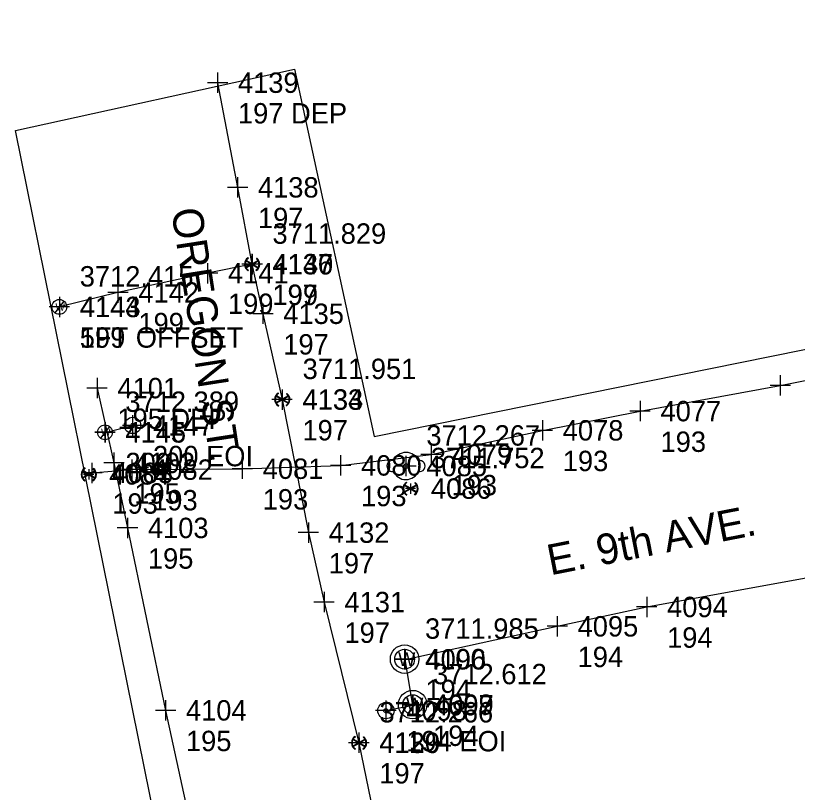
# Model space of a CAD drawing. Extents: x 352921 to 392463, y 10654752 to 10749237.
# Drawn here: x 385296.1 to 385487.7, y 10655239 to 10655429.4 of the extents above; entities that cross this region are included whole.
import ezdxf

# ---------------------------------------------------------------- set-up
doc = ezdxf.new("R2010")
doc.units = 0
for name, color, linetype in [('GAS', 7, 'Continuous'), ('GAS_#', 7, 'Continuous'), ('GAS_DES', 7, 'Continuous'), ('GAS_SPOT', 7, 'Continuous'), ('LIMITS', 7, 'Continuous'), ('ROAD NAMES', 7, 'Continuous'), ('TELE', 7, 'Continuous'), ('TELE_#', 7, 'Continuous'), ('TELE_DES', 7, 'Continuous'), ('TELE_SPOT', 7, 'Continuous'), ('W_#', 7, 'Continuous'), ('W_DES', 7, 'Continuous'), ('W_ELEV', 7, 'Continuous'), ('W_SPOT', 7, 'Continuous'), ('WATER', 7, 'Continuous'), ('WW', 7, 'Continuous'), ('WW_#', 7, 'Continuous'), ('WW_DES', 7, 'Continuous'), ('WW_ELEV', 7, 'Continuous'), ('WW_SPOT', 7, 'Continuous')]:
    doc.layers.add(name, color=color, linetype=linetype)

msp = doc.modelspace()

# ---------------------------------------------------------------- linework, layer by layer
at = {"layer": 'GAS'}
for p, q in [((385312.45, 10655316.11), (385315.58, 10655317.82)), ((385312.47, 10655317.86), (385315.54, 10655316.08)), ((385313.87, 10655316.96), (385312.5, 10655317.76)), ((385314.02, 10655317.04), (385312.57, 10655317.88)), ((385313.13, 10655318.43), (385313.05, 10655318.55)), ((385315.49, 10655317.85), (385314.02, 10655317.04)), ((385315.56, 10655317.72), (385314.17, 10655316.96)), ((385315.15, 10655318.43), (385315.06, 10655318.32)), ((385312.48, 10655316.2), (385313.87, 10655316.96)), ((385312.55, 10655316.08), (385314.02, 10655316.88)), ((385314.02, 10655316.88), (385315.47, 10655316.04)), ((385314.17, 10655316.96), (385315.54, 10655316.16)), ((385314.97, 10655315.53), (385315.05, 10655315.41))]:
    msp.add_line(p, q, dxfattribs=at)
msp.add_lwpolyline([(385314.79, 10655317.32), (385324.56, 10655318.13), (385351.66, 10655318.35), (385375.76, 10655319.16), (385397.95, 10655321.83), (385425.22, 10655327.76), (385449.19, 10655332.47), (385483.56, 10655338.76), (385508.96, 10655343.79)], dxfattribs=at)
for centre, radius, start, end in [((385314.02, 10655316.96), 1.86, 121.3633, 239.9103), ((385314.01, 10655316.96), 1.79, 121.3633, 239.9103), ((385314.02, 10655316.96), 1.71, 152.3305, 206.3323), ((385314.02, 10655316.96), 1.71, 121.3633, 147.5545), ((385314.01, 10655316.96), 1.79, 303.5829, 52.4874), ((385314.02, 10655316.96), 1.86, 303.5829, 52.4874), ((385314.02, 10655316.96), 1.71, 31.1083, 52.4874), ((385314.02, 10655316.96), 1.71, 332.2978, 26.3323), ((385314.02, 10655316.96), 1.71, 211.1083, 239.9103), ((385314.02, 10655316.96), 1.71, 303.5829, 327.5218)]:
    msp.add_arc(centre, radius, start, end, dxfattribs=at)
at = {"layer": 'GAS_SPOT'}
for p, q in [((385483.56, 10655341.26), (385483.56, 10655336.26)), ((385486.06, 10655338.76), (385481.06, 10655338.76)), ((385449.19, 10655334.97), (385449.19, 10655329.97)), ((385451.69, 10655332.47), (385446.69, 10655332.47)), ((385425.22, 10655330.26), (385425.22, 10655325.26)), ((385427.72, 10655327.76), (385422.72, 10655327.76)), ((385397.95, 10655324.33), (385397.95, 10655319.33)), ((385351.66, 10655320.85), (385351.66, 10655315.85)), ((385375.76, 10655321.66), (385375.76, 10655316.66)), ((385400.45, 10655321.83), (385395.45, 10655321.83)), ((385314.79, 10655319.82), (385314.79, 10655314.82)), ((385324.56, 10655320.63), (385324.56, 10655315.63)), ((385378.26, 10655319.16), (385373.26, 10655319.16)), ((385317.29, 10655317.32), (385312.29, 10655317.32)), ((385314.01, 10655318.21), (385314.01, 10655315.71)), ((385327.06, 10655318.13), (385322.06, 10655318.13)), ((385354.16, 10655318.35), (385349.16, 10655318.35)), ((385315.26, 10655316.96), (385312.76, 10655316.96))]:
    msp.add_line(p, q, dxfattribs=at)
at = {"layer": 'LIMITS'}
msp.add_lwpolyline([(385316.84, 10655172.95), (385336.24, 10655202.51), (385296.08, 10655401.3), (385364.42, 10655416.32), (385383.95, 10655326.24), (385639.03, 10655377.81), (385628.06, 10655457.52), (385689.37, 10655471.82), (385708.03, 10655388.94), (385758.43, 10655397.43), (385771.76, 10655335.88), (385725.23, 10655328.36), (385738.81, 10655269.61), (386184.57, 10655359.73)], dxfattribs=at)
at = {"layer": 'TELE'}
msp.add_lwpolyline([(385316.04, 10655338.11), (385320.18, 10655319.79), (385323.51, 10655303.84), (385332.84, 10655259.11), (385338.25, 10655234.32), (385336.55, 10655224.83), (385338.78, 10655215.47), (385342.93, 10655206.36), (385345.06, 10655192.94), (385344.44, 10655182.79), (385341.81, 10655175.01), (385340.48, 10655172.82)], dxfattribs=at)
at = {"layer": 'TELE_SPOT'}
for p, q in [((385316.04, 10655340.61), (385316.04, 10655335.61)), ((385318.54, 10655338.11), (385313.54, 10655338.11)), ((385320.18, 10655322.29), (385320.18, 10655317.29)), ((385322.68, 10655319.79), (385317.68, 10655319.79)), ((385323.51, 10655306.34), (385323.51, 10655301.34)), ((385326.01, 10655303.84), (385321.01, 10655303.84)), ((385332.84, 10655261.61), (385332.84, 10655256.61)), ((385335.34, 10655259.11), (385330.34, 10655259.11))]:
    msp.add_line(p, q, dxfattribs=at)
at = {"layer": 'W_SPOT'}
for p, q in [((385345.59, 10655415.49), (385345.59, 10655410.49)), ((385348.09, 10655412.99), (385343.09, 10655412.99)), ((385350.49, 10655389.83), (385350.49, 10655384.83)), ((385352.99, 10655387.33), (385347.99, 10655387.33)), ((385354.02, 10655371), (385354.02, 10655366)), ((385354.07, 10655370.97), (385354.07, 10655365.97)), ((385343.14, 10655368.78), (385343.14, 10655363.78)), ((385354.05, 10655369.75), (385354.05, 10655367.25)), ((385356.52, 10655368.5), (385351.52, 10655368.5)), ((385356.57, 10655368.47), (385351.57, 10655368.47)), ((385355.3, 10655368.49), (385352.8, 10655368.49)), ((385345.64, 10655366.28), (385340.64, 10655366.28)), ((385321.18, 10655364.05), (385321.18, 10655359.05)), ((385323.68, 10655361.55), (385318.68, 10655361.55)), ((385306.8, 10655360.52), (385306.8, 10655355.52)), ((385306.83, 10655360.51), (385306.83, 10655355.51)), ((385309.3, 10655358.02), (385304.3, 10655358.02)), ((385309.33, 10655358.01), (385304.33, 10655358.01)), ((385356.7, 10655358.84), (385356.7, 10655353.84)), ((385359.2, 10655356.34), (385354.2, 10655356.34)), ((385361.4, 10655337.79), (385361.4, 10655332.79)), ((385361.44, 10655336.58), (385361.44, 10655334.08)), ((385363.9, 10655335.29), (385358.9, 10655335.29)), ((385362.69, 10655335.32), (385360.19, 10655335.32)), ((385324.76, 10655331.45), (385324.76, 10655326.45)), ((385317.98, 10655329.78), (385317.98, 10655324.78)), ((385318, 10655329.75), (385318, 10655324.75)), ((385327.26, 10655328.95), (385322.26, 10655328.95)), ((385320.48, 10655327.28), (385315.48, 10655327.28)), ((385320.5, 10655327.25), (385315.5, 10655327.25)), ((385391.78, 10655321.51), (385391.78, 10655316.51)), ((385394.28, 10655319.01), (385389.28, 10655319.01)), ((385394.13, 10655313.48), (385391.63, 10655313.48)), ((385392.88, 10655314.73), (385392.88, 10655312.23)), ((385367.85, 10655305.18), (385367.85, 10655300.18)), ((385370.35, 10655302.68), (385365.35, 10655302.68)), ((385371.7, 10655288.15), (385371.7, 10655283.15)), ((385374.2, 10655285.65), (385369.2, 10655285.65)), ((385380.23, 10655253.68), (385380.23, 10655248.68)), ((385380.27, 10655252.39), (385380.27, 10655249.89)), ((385382.73, 10655251.18), (385377.73, 10655251.18)), ((385381.52, 10655251.14), (385379.02, 10655251.14))]:
    msp.add_line(p, q, dxfattribs=at)
at = {"layer": 'WATER'}
for p, q in [((385352.49, 10655367.64), (385355.62, 10655369.35)), ((385352.51, 10655369.39), (385355.58, 10655367.61)), ((385353.91, 10655368.49), (385352.54, 10655369.29)), ((385354.06, 10655368.57), (385352.61, 10655369.41)), ((385353.17, 10655369.96), (385353.09, 10655370.08)), ((385355.53, 10655369.38), (385354.06, 10655368.57)), ((385355.59, 10655369.25), (385354.2, 10655368.49)), ((385355.19, 10655369.96), (385355.1, 10655369.85)), ((385352.52, 10655367.73), (385353.91, 10655368.49)), ((385352.59, 10655367.61), (385354.06, 10655368.41)), ((385354.06, 10655368.41), (385355.5, 10655367.57)), ((385354.2, 10655368.49), (385355.58, 10655367.69)), ((385355.01, 10655367.06), (385355.09, 10655366.94)), ((385307.93, 10655359.42), (385305.73, 10655356.54)), ((385359.88, 10655334.47), (385363.01, 10655336.18)), ((385359.9, 10655336.22), (385362.97, 10655334.44)), ((385361.45, 10655335.4), (385360, 10655336.24)), ((385360.56, 10655336.79), (385360.48, 10655336.91)), ((385362.92, 10655336.21), (385361.45, 10655335.4)), ((385362.58, 10655336.79), (385362.49, 10655336.68)), ((385359.91, 10655334.56), (385361.3, 10655335.32)), ((385361.3, 10655335.32), (385359.93, 10655336.12)), ((385359.98, 10655334.44), (385361.45, 10655335.24)), ((385361.45, 10655335.24), (385362.9, 10655334.4)), ((385362.99, 10655336.08), (385361.59, 10655335.32)), ((385361.59, 10655335.32), (385362.97, 10655334.52)), ((385362.4, 10655333.89), (385362.48, 10655333.77)), ((385319.11, 10655328.68), (385316.9, 10655325.8)), ((385318, 10655327.25), (385324.76, 10655328.95)), ((385388.69, 10655317.75), (385388.68, 10655317.68)), ((385391.32, 10655312.62), (385394.45, 10655314.34)), ((385391.34, 10655314.37), (385394.41, 10655312.59)), ((385391.35, 10655312.71), (385392.74, 10655313.48)), ((385392.74, 10655313.48), (385391.37, 10655314.27)), ((385391.42, 10655312.59), (385392.89, 10655313.39)), ((385392.89, 10655313.56), (385391.44, 10655314.39)), ((385392, 10655314.94), (385391.92, 10655315.06)), ((385394.36, 10655314.36), (385392.89, 10655313.56)), ((385392.89, 10655313.39), (385394.34, 10655312.55)), ((385394.43, 10655314.23), (385393.03, 10655313.47)), ((385393.03, 10655313.47), (385394.41, 10655312.68)), ((385394.02, 10655314.95), (385393.93, 10655314.83)), ((385393.84, 10655312.05), (385393.92, 10655311.93)), ((385378.71, 10655250.28), (385381.84, 10655252)), ((385378.73, 10655252.03), (385381.8, 10655250.25)), ((385380.13, 10655251.14), (385378.76, 10655251.93)), ((385380.28, 10655251.22), (385378.83, 10655252.06)), ((385379.39, 10655252.6), (385379.31, 10655252.72)), ((385381.75, 10655252.02), (385380.28, 10655251.22)), ((385381.81, 10655251.9), (385380.42, 10655251.13)), ((385381.41, 10655252.61), (385381.32, 10655252.5)), ((385378.74, 10655250.38), (385380.13, 10655251.14)), ((385378.81, 10655250.25), (385380.28, 10655251.05)), ((385380.28, 10655251.05), (385381.72, 10655250.22)), ((385380.42, 10655251.13), (385381.8, 10655250.34)), ((385381.23, 10655249.71), (385381.31, 10655249.59))]:
    msp.add_line(p, q, dxfattribs=at)
for points in [[(385345.59, 10655412.99), (385350.49, 10655387.33), (385354.02, 10655368.5), (385356.7, 10655356.34), (385361.4, 10655335.29), (385367.85, 10655302.68), (385371.7, 10655285.65), (385380.23, 10655251.18), (385386.03, 10655222.98), (385388.73, 10655209.54), (385391.26, 10655197.76), (385391.98, 10655194.59)], [(385354.07, 10655368.47), (385343.14, 10655366.28), (385321.18, 10655361.55), (385306.83, 10655358.01)]]:
    msp.add_lwpolyline(points, dxfattribs=at)
for centre, radius in [((385306.8, 10655358.02), 1.82), ((385306.8, 10655358.02), 1.82), ((385324.76, 10655328.95), 2), ((385317.98, 10655327.28), 1.82), ((385317.98, 10655327.28), 1.82), ((385324.76, 10655328.95), 0.5), ((385391.78, 10655319.01), 0.57)]:
    msp.add_circle(centre, radius, dxfattribs=at)
for centre, radius, start, end in [((385354.06, 10655368.49), 1.86, 121.3633, 239.9103), ((385354.05, 10655368.49), 1.79, 121.3633, 239.9103), ((385354.06, 10655368.49), 1.71, 152.3305, 206.3323), ((385354.06, 10655368.49), 1.71, 121.3633, 147.5545), ((385354.05, 10655368.49), 1.79, 303.5829, 52.4874), ((385354.06, 10655368.49), 1.86, 303.5829, 52.4874), ((385354.06, 10655368.49), 1.71, 31.1083, 52.4874), ((385354.06, 10655368.49), 1.71, 332.2978, 26.3323), ((385354.06, 10655368.49), 1.71, 211.1083, 239.9103), ((385354.06, 10655368.49), 1.71, 303.5829, 327.5218), ((385361.45, 10655335.32), 1.86, 121.3633, 239.9103), ((385361.44, 10655335.32), 1.79, 121.3633, 239.9103), ((385361.45, 10655335.32), 1.71, 121.3633, 147.5545), ((385361.44, 10655335.32), 1.79, 303.5829, 52.4874), ((385361.45, 10655335.32), 1.86, 303.5829, 52.4874), ((385361.45, 10655335.32), 1.71, 31.1083, 52.4874), ((385361.45, 10655335.32), 1.71, 152.3305, 206.3323), ((385361.45, 10655335.32), 1.71, 211.1083, 239.9103), ((385361.45, 10655335.32), 1.71, 303.5829, 327.5218), ((385361.45, 10655335.32), 1.71, 332.2978, 26.3323), ((385391.78, 10655319.01), 3.33, 22.2367, 157.249), ((385391.78, 10655319.01), 3.33, 22.2367, 157.249), ((385388.44, 10655319.01), 1.35, 74.8142, 280.1755), ((385388.45, 10655319.01), 1.35, 74.8142, 280.1755), ((385395.11, 10655319.01), 1.36, 257.9052, 102.0948), ((385395.11, 10655319.01), 1.36, 257.9052, 102.0948), ((385391.78, 10655319.01), 3.33, 202.2906, 337.9941), ((385391.78, 10655319.01), 3.33, 202.2906, 337.9941), ((385392.89, 10655313.47), 1.86, 121.3633, 239.9103), ((385392.88, 10655313.48), 1.79, 121.3633, 239.9103), ((385392.89, 10655313.47), 1.71, 152.3305, 206.3323), ((385392.89, 10655313.47), 1.71, 121.3633, 147.5545), ((385392.88, 10655313.48), 1.79, 303.5829, 52.4874), ((385392.89, 10655313.47), 1.86, 303.5829, 52.4874), ((385392.89, 10655313.47), 1.71, 31.1083, 52.4874), ((385392.89, 10655313.47), 1.71, 332.2978, 26.3323), ((385392.89, 10655313.47), 1.71, 211.1083, 239.9103), ((385392.89, 10655313.47), 1.71, 303.5829, 327.5218), ((385380.28, 10655251.14), 1.86, 121.3633, 239.9103), ((385380.27, 10655251.14), 1.79, 121.3633, 239.9103), ((385380.28, 10655251.14), 1.71, 152.3305, 206.3323), ((385380.28, 10655251.14), 1.71, 121.3633, 147.5545), ((385380.27, 10655251.14), 1.79, 303.5829, 52.4874), ((385380.28, 10655251.14), 1.86, 303.5829, 52.4874), ((385380.28, 10655251.14), 1.71, 31.1083, 52.4874), ((385380.28, 10655251.14), 1.71, 332.2978, 26.3323), ((385380.28, 10655251.14), 1.71, 211.1083, 239.9103), ((385380.28, 10655251.14), 1.71, 303.5829, 327.5218)]:
    msp.add_arc(centre, radius, start, end, dxfattribs=at)
at = {"layer": 'WW'}
msp.add_lwpolyline([(385386.85, 10655259.05), (385393.44, 10655260.38), (385391.56, 10655271.61), (385428.86, 10655279.71), (385450.8, 10655284.46), (385492.08, 10655291.99), (385522.77, 10655298.68), (385520.55, 10655309.47), (385518.37, 10655321.03), (385514.81, 10655338.51), (385511.18, 10655356.51)], dxfattribs=at)
for centre, radius in [((385391.45, 10655271.66), 3.5), ((385391.45, 10655271.66), 3.5), ((385391.45, 10655271.66), 2.42), ((385393.42, 10655260.51), 3.5), ((385393.42, 10655260.51), 3.5), ((385393.42, 10655260.51), 2.42), ((385386.85, 10655259.05), 2), ((385386.85, 10655259.05), 0.5)]:
    msp.add_circle(centre, radius, dxfattribs=at)
at = {"layer": 'WW_SPOT'}
for p, q in [((385450.8, 10655286.96), (385450.8, 10655281.96)), ((385453.3, 10655284.46), (385448.3, 10655284.46)), ((385428.86, 10655282.21), (385428.86, 10655277.21)), ((385431.36, 10655279.71), (385426.36, 10655279.71)), ((385391.45, 10655274.16), (385391.45, 10655269.16)), ((385391.56, 10655274.11), (385391.56, 10655269.11)), ((385393.95, 10655271.66), (385388.95, 10655271.66)), ((385394.06, 10655271.61), (385389.06, 10655271.61)), ((385386.85, 10655261.55), (385386.85, 10655256.55)), ((385393.42, 10655263.01), (385393.42, 10655258.01)), ((385393.44, 10655262.88), (385393.44, 10655257.88)), ((385395.92, 10655260.51), (385390.92, 10655260.51)), ((385395.94, 10655260.38), (385390.94, 10655260.38)), ((385389.35, 10655259.05), (385384.35, 10655259.05))]:
    msp.add_line(p, q, dxfattribs=at)

# ---------------------------------------------------------------- texts
at = {"layer": 'GAS_#'}
for s, p in [('4077', (385454.19, 10655329.97)), ('4078', (385430.22, 10655325.26)), ('4079', (385402.95, 10655319.33)), ('4081', (385356.66, 10655315.85)), ('4080', (385380.76, 10655316.66)), ('4084', (385319.01, 10655314.46)), ('4083', (385319.79, 10655314.82)), ('4082', (385329.56, 10655315.63))]:
    msp.add_text(s, height=5, dxfattribs=at).set_placement(p)
at = {"layer": 'GAS_DES'}
for p in [(385454.19, 10655322.47), (385430.22, 10655317.76), (385402.95, 10655311.83), (385329.56, 10655308.13), (385356.66, 10655308.35), (385380.76, 10655309.16), (385319.79, 10655307.32)]:
    msp.add_text('193', height=5, dxfattribs=at).set_placement(p)
at = {"layer": 'ROAD NAMES'}
for s, rotation, p in [('OREGON ST.', 278.8204, (385334.22, 10655381.77)), ('E. 9th AVE.', 11.1038, (385427.2, 10655292.19))]:
    msp.add_text(s, height=7.5, rotation=rotation, dxfattribs=at).set_placement(p)
at = {"layer": 'TELE_#'}
for s, p in [('4101', (385321.04, 10655335.61)), ('4102', (385325.18, 10655317.29)), ('4103', (385328.51, 10655301.34)), ('4104', (385337.84, 10655256.61))]:
    msp.add_text(s, height=5, dxfattribs=at).set_placement(p)
at = {"layer": 'TELE_DES'}
for s, p in [('195 DEP', (385321.04, 10655328.11)), ('195', (385325.18, 10655309.79)), ('195', (385328.51, 10655293.84)), ('195', (385337.84, 10655249.11))]:
    msp.add_text(s, height=5, dxfattribs=at).set_placement(p)
at = {"layer": 'W_#'}
for s, p in [('4139', (385350.59, 10655410.49)), ('4138', (385355.49, 10655384.83)), ('4136', (385359.02, 10655366)), ('4137', (385359.05, 10655366)), ('4140', (385359.07, 10655365.97)), ('4141', (385348.14, 10655363.78)), ('4142', (385326.18, 10655359.05)), ('4144', (385311.8, 10655355.52)), ('4143', (385311.83, 10655355.51)), ('4135', (385361.7, 10655353.84)), ('4133', (385366.4, 10655332.79)), ('4134', (385366.44, 10655332.83)), ('4147', (385329.76, 10655326.45)), ('4145', (385322.98, 10655324.78)), ('4146', (385323, 10655324.75)), ('4085', (385396.78, 10655316.51)), ('4086', (385397.88, 10655310.98)), ('4132', (385372.85, 10655300.18)), ('4131', (385376.7, 10655283.15)), ('4129', (385385.23, 10655248.68)), ('4130', (385385.27, 10655248.64))]:
    msp.add_text(s, height=5, dxfattribs=at).set_placement(p)
at = {"layer": 'W_DES'}
for s, p in [('197 DEP', (385350.59, 10655402.99)), ('197', (385355.49, 10655377.33)), ('197', (385359.02, 10655358.5)), ('199', (385359.07, 10655358.47)), ('199', (385348.14, 10655356.28)), ('199', (385326.18, 10655351.55)), ('5FT OFFSET', (385311.8, 10655348.02)), ('199', (385311.83, 10655348.01)), ('197', (385361.7, 10655346.34)), ('197', (385366.4, 10655325.29)), ('200 EOI', (385329.76, 10655318.95)), ('200', (385323, 10655317.25)), ('197', (385372.85, 10655292.68)), ('197', (385376.7, 10655275.65)), ('197', (385385.23, 10655241.18))]:
    msp.add_text(s, height=5, dxfattribs=at).set_placement(p)
at = {"layer": 'W_ELEV'}
for s, p in [('3711.829', (385359.05, 10655373.5)), ('3712.415', (385311.8, 10655363.02)), ('3711.951', (385366.44, 10655340.33)), ('3712.389', (385322.98, 10655332.28)), ('3712.267', (385396.78, 10655324.01)), ('3711.752', (385397.88, 10655318.48)), ('3712.266', (385385.27, 10655256.14))]:
    msp.add_text(s, height=5, dxfattribs=at).set_placement(p)
at = {"layer": 'WATER'}
for p in [(385305.85, 10655357.07), (385317.03, 10655326.33)]:
    msp.add_text('W', height=1.82, dxfattribs=at).set_placement(p)
at = {"layer": 'WW'}
for p in [(385389.87, 10655270), (385391.84, 10655258.85)]:
    msp.add_text('W', height=3.33, dxfattribs=at).set_placement(p)
at = {"layer": 'WW_#'}
for s, p in [('4094', (385455.8, 10655281.96)), ('4095', (385433.86, 10655277.21)), ('4100', (385396.45, 10655269.16)), ('4096', (385396.56, 10655269.11)), ('4098', (385391.85, 10655256.55)), ('4099', (385398.42, 10655258.01)), ('4097', (385398.44, 10655257.88))]:
    msp.add_text(s, height=5, dxfattribs=at).set_placement(p)
at = {"layer": 'WW_DES'}
for s, p in [('194', (385455.8, 10655274.46)), ('194', (385433.86, 10655269.71)), ('194', (385396.56, 10655261.61)), ('194 EOI', (385391.85, 10655249.05)), ('194', (385398.44, 10655250.38))]:
    msp.add_text(s, height=5, dxfattribs=at).set_placement(p)
at = {"layer": 'WW_ELEV'}
for s, p in [('3711.985', (385396.45, 10655276.66)), ('3712.612', (385398.42, 10655265.51))]:
    msp.add_text(s, height=5, dxfattribs=at).set_placement(p)

doc.saveas('drawing.dxf')
